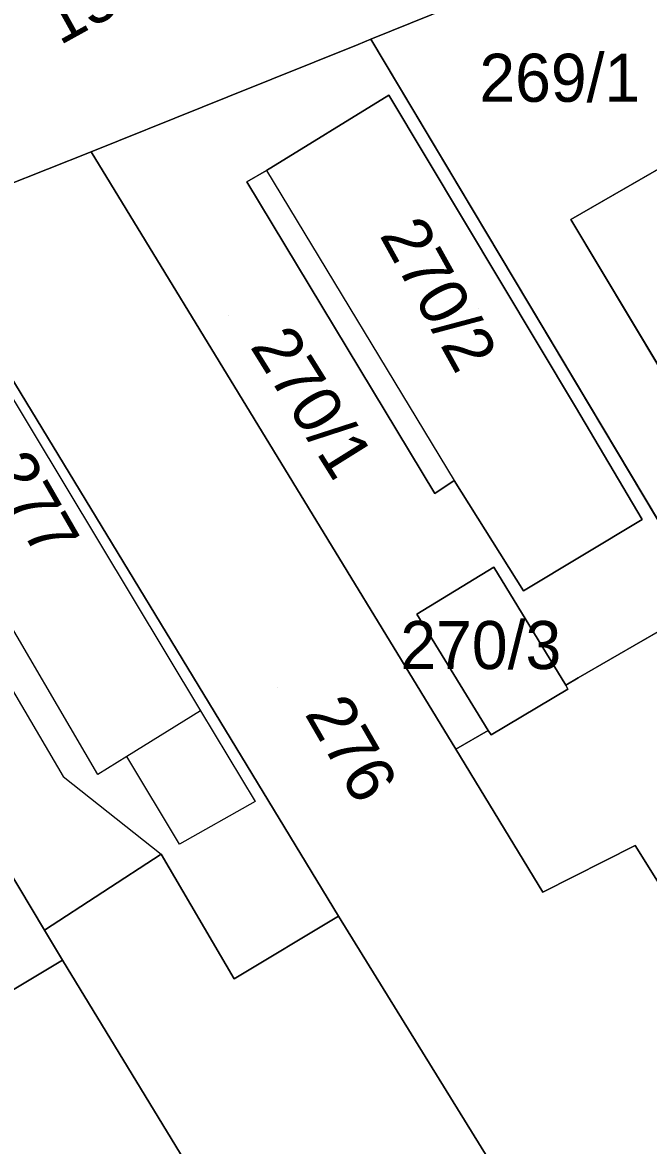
# Model space of a CAD drawing. Extents: x -263943 to -261149, y -1236934 to -1230686.
# Drawn here: x -262535.5 to -262509.47, y -1235603.42 to -1235556.72 of the extents above; entities that cross this region are included whole.
import ezdxf

# ---------------------------------------------------------------- set-up
doc = ezdxf.new("R2010")
doc.units = 0
for name, color, linetype in [('body_kn', 7, 'Continuous'), ('kladpar_druhypozemkov', 7, 'Continuous'), ('kladpar_hranice', 7, 'Continuous'), ('kladpar_parcelnecisla', 7, 'Continuous'), ('kladpar_plochy', 7, 'Continuous'), ('zappar_hrandruhpozemk', 7, 'Continuous')]:
    doc.layers.add(name, color=color, linetype=linetype)

msp = doc.modelspace()

# ---------------------------------------------------------------- linework, layer by layer
at = {"layer": 'body_kn'}
for p, q in [((-262521.54, -1235557.63), (-262521.54, -1235557.63)), ((-262521.02, -1235557.42), (-262521.02, -1235557.42)), ((-262526.96, -1235559.81), (-262526.96, -1235559.81)), ((-262526.96, -1235559.81), (-262526.96, -1235559.81)), ((-262520.27, -1235559.75), (-262520.27, -1235559.75)), ((-262520.27, -1235559.75), (-262520.27, -1235559.75)), ((-262528.03, -1235560.24), (-262528.03, -1235560.24)), ((-262532.65, -1235562.1), (-262532.65, -1235562.1)), ((-262525.36, -1235562.88), (-262525.36, -1235562.88)), ((-262525.36, -1235562.88), (-262525.36, -1235562.88)), ((-262526.17, -1235563.35), (-262526.17, -1235563.35)), ((-262512.7, -1235564.91), (-262512.7, -1235564.91)), ((-262512.51, -1235572.7), (-262512.51, -1235572.7)), ((-262517.55, -1235575.77), (-262517.55, -1235575.77)), ((-262518.36, -1235576.31), (-262518.36, -1235576.31)), ((-262509.74, -1235577.39), (-262509.74, -1235577.39)), ((-262515.91, -1235579.37), (-262515.91, -1235579.37)), ((-262514.67, -1235580.35), (-262514.67, -1235580.35)), ((-262519.11, -1235581.33), (-262519.11, -1235581.33)), ((-262512.91, -1235584.28), (-262512.91, -1235584.28)), ((-262512.91, -1235584.28), (-262512.91, -1235584.28)), ((-262512.39, -1235583.98), (-262512.39, -1235583.98)), ((-262512.82, -1235584.44), (-262512.82, -1235584.44)), ((-262528.1, -1235585.34), (-262528.1, -1235585.34)), ((-262516.14, -1235586.16), (-262516.14, -1235586.16)), ((-262516.02, -1235586.35), (-262516.02, -1235586.35)), ((-262516.02, -1235586.35), (-262516.02, -1235586.35)), ((-262517.49, -1235586.94), (-262517.49, -1235586.94)), ((-262531.16, -1235587.24), (-262531.16, -1235587.24)), ((-262531.16, -1235587.24), (-262531.16, -1235587.24)), ((-262533.81, -1235588.07), (-262533.81, -1235588.07)), ((-262532.37, -1235587.99), (-262532.37, -1235587.99)), ((-262525.83, -1235589.12), (-262525.83, -1235589.12)), ((-262528.98, -1235590.89), (-262528.98, -1235590.89)), ((-262529.74, -1235591.31), (-262529.74, -1235591.31)), ((-262529.74, -1235591.31), (-262529.74, -1235591.31)), ((-262510.03, -1235590.95), (-262510.03, -1235590.95)), ((-262513.86, -1235592.89), (-262513.86, -1235592.89)), ((-262522.36, -1235593.88), (-262522.36, -1235593.88)), ((-262534.59, -1235594.46), (-262534.59, -1235594.46)), ((-262533.84, -1235595.71), (-262533.84, -1235595.71)), ((-262526.7, -1235596.49), (-262526.7, -1235596.49))]:
    msp.add_line(p, q, dxfattribs=at)
at = {"layer": 'kladpar_druhypozemkov'}
for p, q in [((-262512.68, -1235558.04), (-262512.68, -1235558.04)), ((-262526.92, -1235568.9), (-262526.92, -1235568.9)), ((-262516.55, -1235568.6), (-262516.55, -1235568.6)), ((-262515.66, -1235581.62), (-262515.66, -1235581.62)), ((-262524.9, -1235584.39), (-262524.9, -1235584.39))]:
    msp.add_line(p, q, dxfattribs=at)
at = {"layer": 'kladpar_hranice'}
msp.add_line((-262528.03, -1235560.24), (-262526.96, -1235559.81), dxfattribs=at)
for points in [[(-262509.2, -1235552.61), (-262508.17, -1235554.35), (-262494.64, -1235577.23), (-262493.08, -1235579.87), (-262493.43, -1235580.08), (-262498.42, -1235583.03), (-262493.65, -1235590.8), (-262498.89, -1235594.95), (-262498.9, -1235594.93), (-262507.02, -1235580.87), (-262521.02, -1235557.42), (-262516.86, -1235555.72), (-262515.67, -1235555.39)], [(-262516.86, -1235555.72), (-262521.02, -1235557.42), (-262521.54, -1235557.63), (-262526.96, -1235559.81), (-262528.03, -1235560.24), (-262532.65, -1235562.1), (-262539.93, -1235564.98)], [(-262526.96, -1235559.81), (-262521.54, -1235557.63), (-262521.02, -1235557.42), (-262507.02, -1235580.87), (-262512.39, -1235583.98), (-262512.91, -1235584.28), (-262515.91, -1235579.37), (-262519.11, -1235581.33), (-262516.14, -1235586.16), (-262517.49, -1235586.94), (-262532.65, -1235562.1), (-262528.03, -1235560.24)], [(-262520.27, -1235559.75), (-262512.51, -1235572.7), (-262509.74, -1235577.39), (-262514.67, -1235580.35), (-262517.55, -1235575.77), (-262518.36, -1235576.31), (-262526.17, -1235563.35), (-262525.36, -1235562.88), (-262520.27, -1235559.75)], [(-262520.27, -1235559.75), (-262525.36, -1235562.88), (-262526.17, -1235563.35), (-262518.36, -1235576.31), (-262517.55, -1235575.77), (-262514.67, -1235580.35), (-262509.74, -1235577.39), (-262512.51, -1235572.7), (-262520.27, -1235559.75)], [(-262505.19, -1235560.59), (-262512.7, -1235564.91), (-262502.74, -1235581.56), (-262495.22, -1235577.31), (-262505.19, -1235560.59)], [(-262505.19, -1235560.59), (-262495.22, -1235577.31), (-262502.74, -1235581.56), (-262512.7, -1235564.91), (-262505.19, -1235560.59)], [(-262505.95, -1235610.1), (-262507.84, -1235611.24), (-262510.61, -1235612.92), (-262522.36, -1235593.88), (-262538.27, -1235567.71), (-262539.93, -1235564.98), (-262532.65, -1235562.1), (-262517.49, -1235586.94), (-262513.86, -1235592.89), (-262510.03, -1235590.95), (-262500.23, -1235606.63), (-262502.65, -1235608.1), (-262505.95, -1235610.1)], [(-262529.74, -1235591.31), (-262534.59, -1235594.46), (-262540.33, -1235584.88), (-262548.87, -1235570.63), (-262550.31, -1235568.5), (-262546.13, -1235566.81), (-262540.35, -1235564.47), (-262539.93, -1235564.98), (-262538.27, -1235567.71), (-262522.36, -1235593.88), (-262526.7, -1235596.49), (-262529.74, -1235591.31)], [(-262538.78, -1235598.66), (-262543.13, -1235602.55), (-262549.04, -1235591.67), (-262552.53, -1235593.86), (-262564.18, -1235574.14), (-262559.42, -1235572.29), (-262550.6, -1235568.62), (-262550.31, -1235568.5), (-262548.87, -1235570.63), (-262540.33, -1235584.88), (-262534.59, -1235594.46), (-262533.84, -1235595.71), (-262538.78, -1235598.66)], [(-262514.59, -1235632.84), (-262528.73, -1235641.53), (-262542, -1235620.28), (-262569.31, -1235576.04), (-262564.18, -1235574.14), (-262552.53, -1235593.86), (-262549.04, -1235591.67), (-262543.13, -1235602.55), (-262538.78, -1235598.66), (-262533.84, -1235595.71), (-262512.13, -1235631.34), (-262514.59, -1235632.84)], [(-262512.91, -1235584.28), (-262512.82, -1235584.44), (-262516.02, -1235586.35), (-262516.14, -1235586.16), (-262519.11, -1235581.33), (-262515.91, -1235579.37), (-262512.91, -1235584.28)], [(-262516.02, -1235586.35), (-262512.82, -1235584.44), (-262512.91, -1235584.28), (-262512.39, -1235583.98), (-262507.02, -1235580.87), (-262498.9, -1235594.93), (-262498.89, -1235594.95), (-262484.52, -1235618.05), (-262490.7, -1235621.87), (-262493.84, -1235616.84), (-262498.96, -1235608.66), (-262500.23, -1235606.63), (-262510.03, -1235590.95), (-262513.86, -1235592.89), (-262517.49, -1235586.94), (-262516.14, -1235586.16), (-262516.02, -1235586.35)], [(-262504.3, -1235623.37), (-262502.89, -1235625.71), (-262512.13, -1235631.34), (-262533.84, -1235595.71), (-262534.59, -1235594.46), (-262529.74, -1235591.31), (-262526.7, -1235596.49), (-262522.36, -1235593.88), (-262510.61, -1235612.92), (-262504.3, -1235623.37)]]:
    msp.add_lwpolyline(points, dxfattribs=at)
at = {"layer": 'kladpar_plochy'}
for p, q in [((-262521.02, -1235557.42), (-262516.86, -1235555.72)), ((-262526.96, -1235559.81), (-262521.54, -1235557.63)), ((-262521.54, -1235557.63), (-262521.02, -1235557.42)), ((-262521.02, -1235557.42), (-262507.02, -1235580.87)), ((-262507.02, -1235580.87), (-262521.02, -1235557.42)), ((-262528.03, -1235560.24), (-262526.96, -1235559.81)), ((-262520.27, -1235559.75), (-262525.36, -1235562.88)), ((-262512.51, -1235572.7), (-262520.27, -1235559.75)), ((-262532.65, -1235562.1), (-262528.03, -1235560.24)), ((-262505.19, -1235560.59), (-262512.7, -1235564.91)), ((-262517.49, -1235586.94), (-262532.65, -1235562.1)), ((-262525.36, -1235562.88), (-262526.17, -1235563.35)), ((-262526.17, -1235563.35), (-262518.36, -1235576.31)), ((-262512.7, -1235564.91), (-262502.74, -1235581.56)), ((-262509.74, -1235577.39), (-262512.51, -1235572.7)), ((-262518.36, -1235576.31), (-262517.55, -1235575.77)), ((-262517.55, -1235575.77), (-262514.67, -1235580.35)), ((-262514.67, -1235580.35), (-262509.74, -1235577.39)), ((-262515.91, -1235579.37), (-262519.11, -1235581.33)), ((-262512.91, -1235584.28), (-262515.91, -1235579.37)), ((-262507.02, -1235580.87), (-262512.39, -1235583.98)), ((-262519.11, -1235581.33), (-262516.14, -1235586.16)), ((-262512.39, -1235583.98), (-262512.91, -1235584.28)), ((-262516.14, -1235586.16), (-262517.49, -1235586.94))]:
    msp.add_line(p, q, dxfattribs=at)
msp.add_lwpolyline([(-262516.86, -1235555.72), (-262521.02, -1235557.42), (-262521.54, -1235557.63), (-262526.96, -1235559.81), (-262528.03, -1235560.24), (-262532.65, -1235562.1), (-262539.93, -1235564.98)], dxfattribs=at)
for points in [[(-262520.27, -1235559.75), (-262512.51, -1235572.7), (-262509.74, -1235577.39), (-262514.67, -1235580.35), (-262517.55, -1235575.77), (-262518.36, -1235576.31), (-262526.17, -1235563.35), (-262525.36, -1235562.88)], [(-262505.19, -1235560.59), (-262495.22, -1235577.31), (-262502.74, -1235581.56), (-262512.7, -1235564.91)], [(-262505.95, -1235610.1), (-262507.84, -1235611.24), (-262510.61, -1235612.92), (-262522.36, -1235593.88), (-262538.27, -1235567.71), (-262539.93, -1235564.98), (-262532.65, -1235562.1), (-262517.49, -1235586.94), (-262513.86, -1235592.89), (-262510.03, -1235590.95), (-262500.23, -1235606.63), (-262502.65, -1235608.1)], [(-262529.74, -1235591.31), (-262534.59, -1235594.46), (-262540.33, -1235584.88), (-262548.87, -1235570.63), (-262550.31, -1235568.5), (-262546.13, -1235566.81), (-262540.35, -1235564.47), (-262539.93, -1235564.98), (-262538.27, -1235567.71), (-262522.36, -1235593.88), (-262526.7, -1235596.49)], [(-262538.78, -1235598.66), (-262543.13, -1235602.55), (-262549.04, -1235591.67), (-262552.53, -1235593.86), (-262564.18, -1235574.14), (-262559.42, -1235572.29), (-262550.6, -1235568.62), (-262550.31, -1235568.5), (-262548.87, -1235570.63), (-262540.33, -1235584.88), (-262534.59, -1235594.46), (-262533.84, -1235595.71)], [(-262514.59, -1235632.84), (-262528.73, -1235641.53), (-262542, -1235620.28), (-262569.31, -1235576.04), (-262564.18, -1235574.14), (-262552.53, -1235593.86), (-262549.04, -1235591.67), (-262543.13, -1235602.55), (-262538.78, -1235598.66), (-262533.84, -1235595.71), (-262512.13, -1235631.34)], [(-262512.91, -1235584.28), (-262512.82, -1235584.44), (-262516.02, -1235586.35), (-262516.14, -1235586.16), (-262519.11, -1235581.33), (-262515.91, -1235579.37)], [(-262516.02, -1235586.35), (-262512.82, -1235584.44), (-262512.91, -1235584.28), (-262512.39, -1235583.98), (-262507.02, -1235580.87), (-262498.9, -1235594.93), (-262498.89, -1235594.95), (-262484.52, -1235618.05), (-262490.7, -1235621.87), (-262493.84, -1235616.84), (-262498.96, -1235608.66), (-262500.23, -1235606.63), (-262510.03, -1235590.95), (-262513.86, -1235592.89), (-262517.49, -1235586.94), (-262516.14, -1235586.16)], [(-262504.3, -1235623.37), (-262502.89, -1235625.71), (-262512.13, -1235631.34), (-262533.84, -1235595.71), (-262534.59, -1235594.46), (-262529.74, -1235591.31), (-262526.7, -1235596.49), (-262522.36, -1235593.88), (-262510.61, -1235612.92)]]:
    msp.add_lwpolyline(points, close=True, dxfattribs=at)
at = {"layer": 'zappar_hrandruhpozemk'}
for p, q in [((-262525.36, -1235562.88), (-262517.55, -1235575.77)), ((-262538.59, -1235567.91), (-262528.1, -1235585.34)), ((-262538.03, -1235580.94), (-262533.81, -1235588.07)), ((-262528.1, -1235585.34), (-262531.16, -1235587.24)), ((-262531.16, -1235587.24), (-262532.37, -1235587.99)), ((-262533.81, -1235588.07), (-262529.74, -1235591.31))]:
    msp.add_line(p, q, dxfattribs=at)
for points in [[(-262532.37, -1235587.99), (-262536.89, -1235580.29), (-262539.18, -1235576.39), (-262542.71, -1235570.38)], [(-262528.1, -1235585.34), (-262525.83, -1235589.12), (-262528.98, -1235590.89), (-262531.16, -1235587.24)]]:
    msp.add_lwpolyline(points, dxfattribs=at)

# ---------------------------------------------------------------- texts
at = {"layer": 'kladpar_parcelnecisla'}
for s, rotation, p in [('1584/10', 29, (-262533.953, -1235557.689)), ('1584/11', 23, (-262540.099, -1235558.046)), ('270/2', 299, (-262520.679, -1235565.564)), ('270/1', 302, (-262526.069, -1235570.192)), ('277', 300, (-262537.022, -1235575.306)), ('276', 300, (-262523.795, -1235585.465))]:
    msp.add_text(s, height=2, rotation=rotation, dxfattribs=at).set_placement(p)
for s, p in [('269/1', (-262516.506, -1235560.02)), ('270/3', (-262519.792, -1235583.61))]:
    msp.add_text(s, height=2, dxfattribs=at).set_placement(p)

doc.saveas('drawing.dxf')
